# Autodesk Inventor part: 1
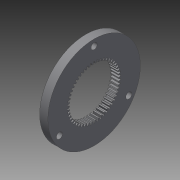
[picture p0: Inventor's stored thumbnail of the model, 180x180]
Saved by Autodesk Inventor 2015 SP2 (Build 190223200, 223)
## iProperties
Created: 2012-07
Part Number: 1
Material: Messing, weicher Gelbton
Vendor: maedler.de
Document SubType Name: Modeling
Designer: rYan
Mass: 36.461 g
Surface Area: 34.7249 cm^2
Volume: 4.30472 cm^3
Density: 8.47 g/cm^3
Appearance: Messing - satiniert
Übersetzungsnorm: STEP AP214IS
Dateiname: c:/PPEXPORT/antriebselemente_und_normteile/innenkraenze/artikel_nr___26145000.stp
Postprozessor: Build: 138, Release: 2013 RTM - Date: Thu 03/01/2012
Gesendete Einheiten: Millimeter
Unbestimmtheit: 1.0000000000000002e-06
Author: rYan
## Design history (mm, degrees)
node "11"
sketch "Skizze1"
  geometry: L1 (31.5, 0)-(-31.5, 0) reference; C1 r 1.5 at (-8.829, 17.387) reference; A1 r 13.05 centre (0, 0) between (-3.774, 12.492) and (-4.289, 12.325) reference; 2 further points
  constraints: 1 centre point, 1 point on line, 1 other
  dimensions: "d11" = 19.5 distance of A1.centre point (-19.5, 0)
hole "Bohrung1" sketch "Skizze1" at (-19.5, 0) diameter "d0" = 3; stored, may be unused: countersink angle "d4" = 90 deg, drill point angle "d6" = 118 deg; dims "d1" = 6, "d2" = 4, "d3" = 2, "d5" = 8
pattern_circular "Runde Anordnung1" dims angle "d8" = 360 deg
node "1"
node "Basis1"
